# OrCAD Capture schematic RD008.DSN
size A3
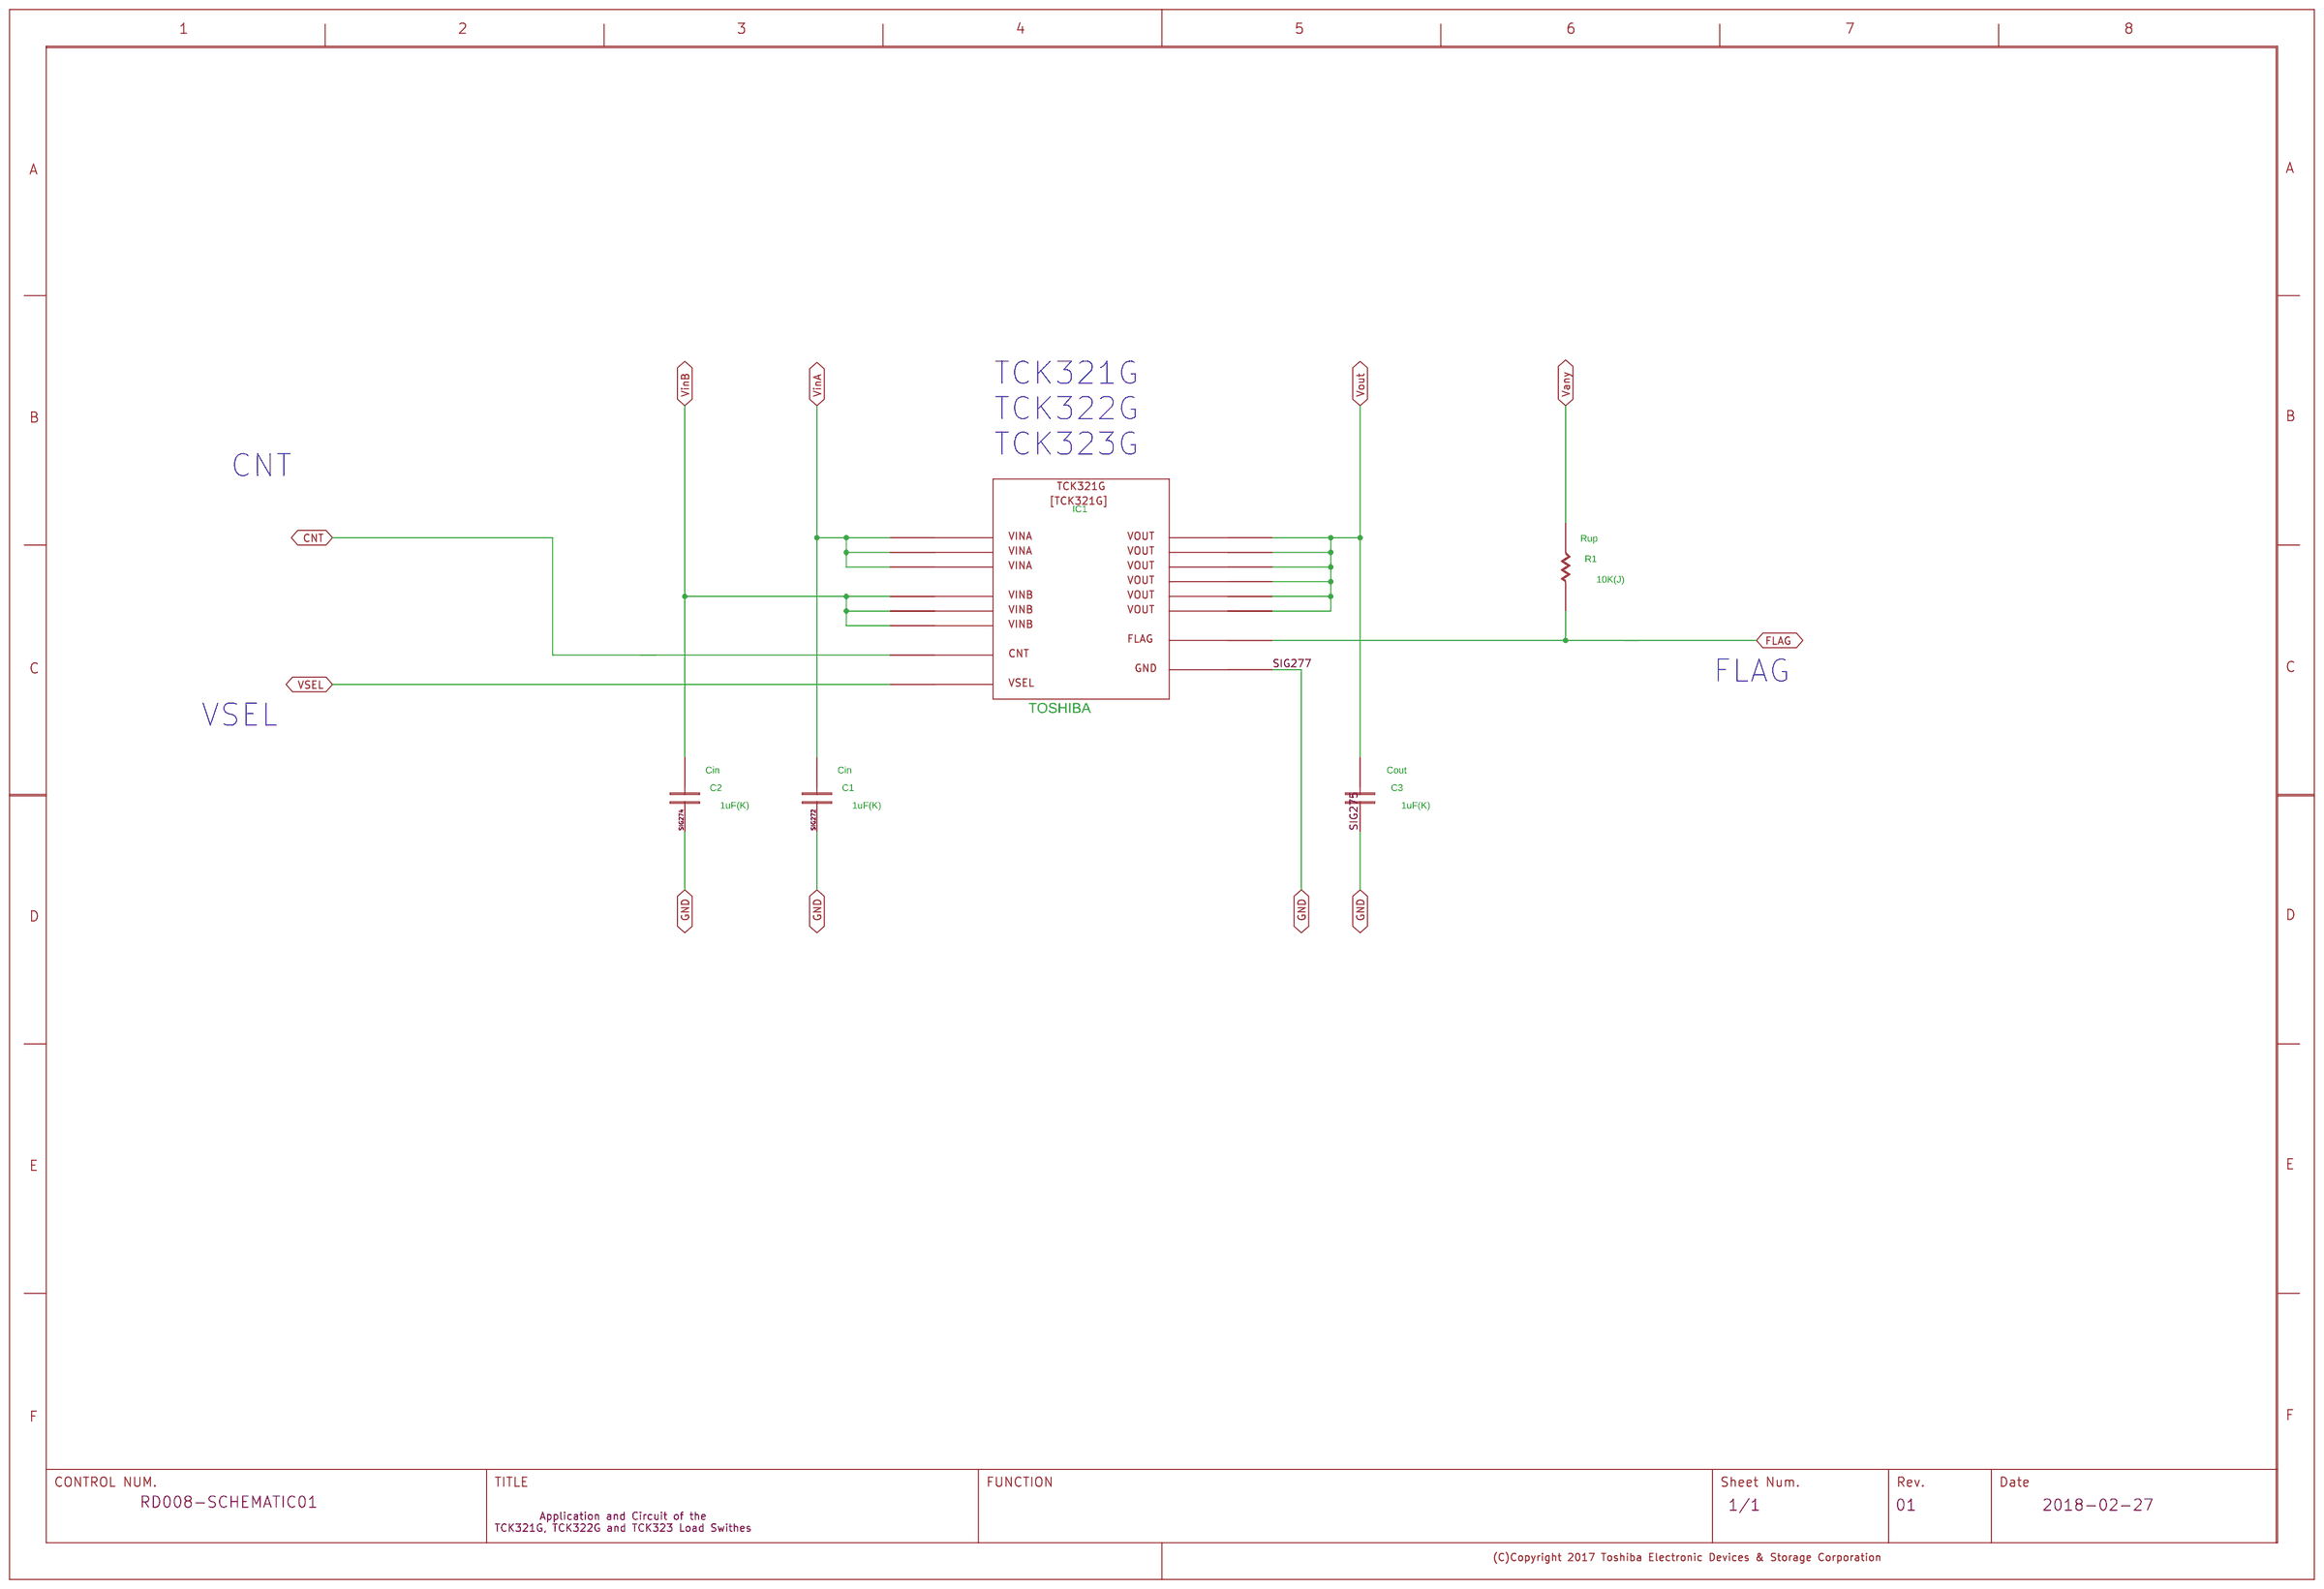
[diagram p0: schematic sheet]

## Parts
C1  C
C2  C
C3  C
IC1  S-TCK321G
R1  R
U?#1  WAKU_DEF100

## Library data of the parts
C1 C2 = C: COMP: PRT_3; COMPONENTTYPE: 4; GCOUNT: 1; MAXGCOUNT: 1; SIZECODESMD: 3216; USERCOMPTEXT1: Cin; VAL1: 1uF(K); VAL2: 50V; VAL3: GRM31MR71H105KA88L
C3 = C: COMP: PRT_3; COMPONENTTYPE: 4; GCOUNT: 1; MAXGCOUNT: 1; SIZECODESMD: 3216; USERCOMPTEXT1: Cout; VAL1: 1uF(K); VAL2: 50V; VAL3: GRM31MR71H105KA88L
IC1 = S-TCK321G: COMP: PRT_1; COMPONENTTYPE: 4; USERCOMPTEXT3: TOSHIBA
R1 = R: COMP: PRT_2; COMPONENTTYPE: 4; GCOUNT: 1; MAXGCOUNT: 1; SIZECODESMD: 1005; USERCOMPTEXT1: Rup; VAL1: 10K(J); VAL2: 63mW; VAL3: CR10-103JV
U?#1 = WAKU_DEF100: COMPONENTTYPE: 2; DATE: 2018-02-27; DRAWINGNUMBER: RD008-SCHEMATIC01; FUNCTION: 2-Power monitoring/selecting circuit; REVISION: 01; SHEETNUMBER: 1/1; TITLE: Application and Circuit of the / TCK321G, TCK322G and TCK323 Load Swithes; UPDATEDATE: 2018/03/01; UPDATETIME: 13:51:40; UPDATEUSER: f1043010

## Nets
GND: C1.1 C2.1 C3.1 IC1.A4
VinA: C1.2 IC1.B1 IC1.C1 IC1.D1
VinB: C2.2 IC1.B4 IC1.C4 IC1.D4
CNT: IC1.A3
FLAG: IC1.A1 R1.1
Vany: R1.2
Vout: C3.2 IC1.B2 IC1.B3 IC1.C2 IC1.C3 IC1.D2 IC1.D3
VSEL: IC1.A2

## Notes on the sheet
- TCK321G
  TCK322G
  TCK323G
- CNT
- FLAG
- VSEL
